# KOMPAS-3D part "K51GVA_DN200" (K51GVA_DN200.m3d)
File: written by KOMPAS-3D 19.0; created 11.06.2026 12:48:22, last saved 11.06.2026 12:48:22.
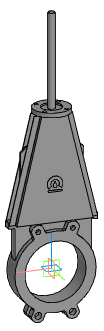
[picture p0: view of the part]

Document properties: Автор: Энергия; Полное имя файла: Z:\3.Личные\kachalov\001_3d для проектировщиков\2.6 Тип_K51GVA. Задвижка\_stp\_stp_K51GVA_DN50-DN1000_с фланцем\K51GVA_DN200.m3d

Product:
- Part/product: K51GVA_DN200

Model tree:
1. Операция без истории:1  (labels: K51GVA_DN200)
